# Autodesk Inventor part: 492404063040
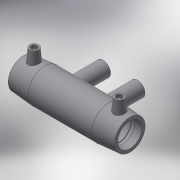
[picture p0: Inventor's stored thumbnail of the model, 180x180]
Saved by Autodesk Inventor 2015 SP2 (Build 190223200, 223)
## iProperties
Created: 2017-06
Part Number: 492404063040
Material: Generic
Description: PLASSON REDUCING TEE WITH TWO OUTLETS 63X40X40X63
Document SubType Name: Modeling
Designer: KIM
Mass: 57.3761 g
Surface Area: 241.06 cm^2
Volume: 57.3761 cm^3
Density: 1 g/cm^3
Appearance: Default
Author: KIM
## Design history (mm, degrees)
derived "492404.ipt"
feature "Solid1::492404.ipt"
tag "TaggingFeature1"
body "Solid1"
other parameters: "d0" = 213, "d1" = 63, "d2" = 82, "d3" = 58, "d4" = 42.6, "d5" = 73.8, "d6" = 59.85, "d7" = 63, "d8" = 168 deg, "d10" = 23.2, "d11" = 7.73333, "d23" = 82, "d29" = 57, "d30" = 15, "d31" = 85.2, "d34" = 5 deg, "d41" = 4, "d42" = 14, "d43" = 0, "d48" = -96, "d51" = 0, "d62" = 96, "d74" = -96, "d85" = 65, "d86" = 32.5, "d87" = 32, "d88" = 32, "d90" = 0, "d91" = 3, "d92" = 0, "d_" = 63, "L_" = 213, "L_1" = 58, "D_" = 82, "A_" = 57, "d_2" = 12, "H_" = 96, "L_2" = 65
